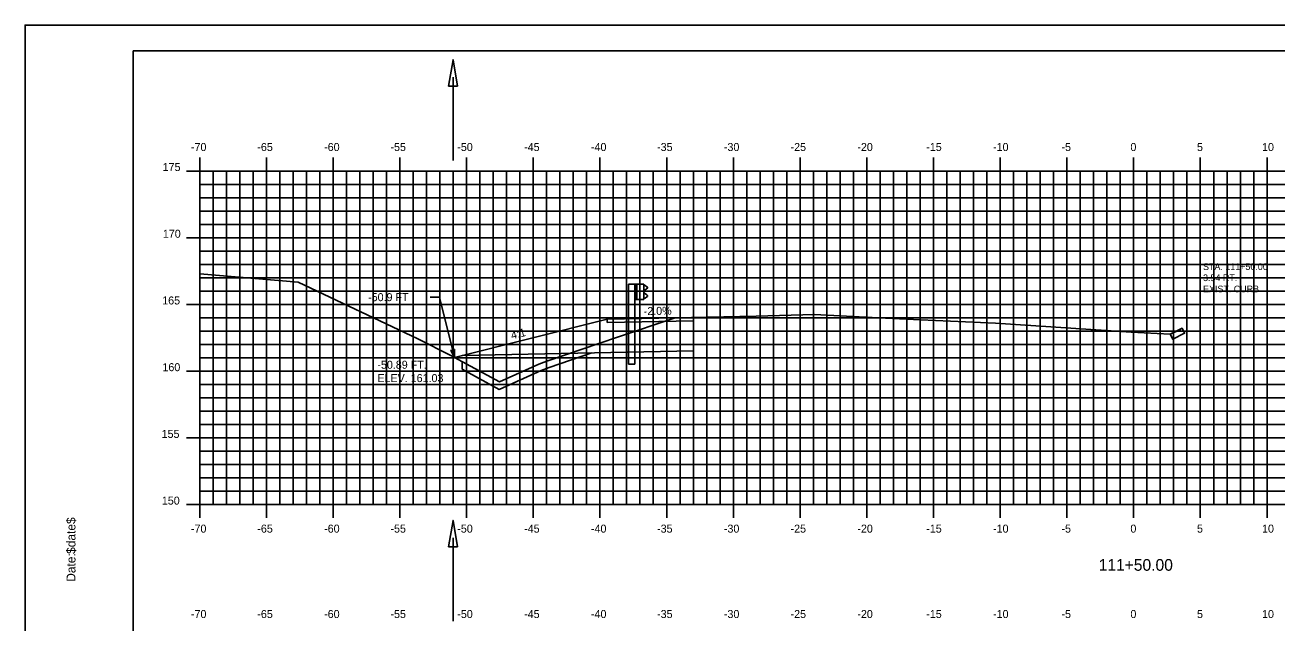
# Model space of a CAD drawing. Extents: x 1668473 to 1668643, y 337823 to 337933.
# Drawn here: x 1668472.7 to 1668566.5, y 337888.6 to 337933.4 of the extents above; entities that cross this region are included whole.
import ezdxf

# ---------------------------------------------------------------- set-up
doc = ezdxf.new("R2010")
doc.units = 0
for name, color, linetype in [('ANNOTATION', 7, 'Continuous'), ('BORDER', 7, 'Continuous'), ('D_Drainage_Ditch_Line', 7, 'Continuous'), ('D_Guardrail_Beam_Lt', 7, 'Continuous'), ('D_Roadway_Pavement', 7, 'Continuous'), ('D_Text_Monospaced', 7, 'Continuous'), ('D_Text_Standard', 7, 'Continuous'), ('Grubbing', 7, 'Continuous'), ('H_V ANNOTATION', 7, 'Continuous'), ('MAJOR', 7, 'Continuous'), ('MINOR', 7, 'Continuous'), ('PLOT BOUNDARY', 7, 'Continuous'), ('S_Curb_Type_5', 7, 'Continuous'), ('S_Roadway_Centerline', 7, 'Continuous')]:
    doc.layers.add(name, color=color, linetype=linetype)

msp = doc.modelspace()

# ---------------------------------------------------------------- linework, layer by layer
at = {"layer": 'ANNOTATION'}
msp.add_line((1668516.335, 337911.092), (1668516.335, 337911.342), dxfattribs=at)
at = {"layer": 'BORDER'}
for p, q in [((1668640.786, 337931.453), (1668480.786, 337931.453)), ((1668480.786, 337931.453), (1668480.786, 337826.453))]:
    msp.add_line(p, q, dxfattribs=at)
at = {"layer": 'D_Drainage_Ditch_Line'}
for p, q in [((1668504.771, 337929.478), (1668504.772, 337923.234)), ((1668504.771, 337894.955), (1668504.772, 337888.712))]:
    msp.add_line(p, q, dxfattribs=at)
for points in [[(1668504.443, 337928.822), (1668505.099, 337928.822), (1668504.771, 337930.79)], [(1668504.443, 337894.299), (1668505.099, 337894.299), (1668504.771, 337896.268)]]:
    msp.add_lwpolyline(points, close=True, dxfattribs=at)
at = {"layer": 'D_Guardrail_Beam_Lt'}
for p, q in [((1668517.916, 337913.986), (1668517.916, 337907.986)), ((1668518.387, 337913.986), (1668517.916, 337913.986)), ((1668519.075, 337913.986), (1668518.387, 337913.986)), ((1668518.387, 337913.986), (1668518.387, 337912.819)), ((1668518.45, 337913.986), (1668518.45, 337912.819)), ((1668518.554, 337913.986), (1668518.554, 337912.819)), ((1668519.075, 337912.819), (1668519.075, 337913.986)), ((1668519.075, 337913.902), (1668519.149, 337913.888)), ((1668519.079, 337913.438), (1668519.079, 337913.367)), ((1668519.308, 337913.638), (1668519.113, 337913.502)), ((1668519.113, 337913.303), (1668519.308, 337913.167)), ((1668519.165, 337913.881), (1668519.308, 337913.781)), ((1668518.387, 337912.819), (1668519.075, 337912.819)), ((1668518.408, 337907.986), (1668518.408, 337912.819)), ((1668519.149, 337912.917), (1668519.075, 337912.902)), ((1668519.308, 337913.024), (1668519.165, 337912.924)), ((1668518.408, 337907.986), (1668517.916, 337907.986))]:
    msp.add_line(p, q, dxfattribs=at)
for centre, major_axis, start_param, end_param in [((1668519.158, 337913.438), (-0.0789, 0), 5.323254, 6.283185), ((1668519.158, 337913.367), (-0.0789, 0), 6.283185, 7.243116), ((1668519.141, 337913.847), (0.0417, 0), 0.959931, 1.376053), ((1668519.258, 337913.71), (0.0877, 0), 5.323254, 7.243116), ((1668519.141, 337912.958), (0.0417, 0), 4.907132, 5.323254), ((1668519.258, 337913.095), (0.0877, 0), 5.323254, 7.243116)]:
    msp.add_ellipse(centre, major_axis=major_axis, ratio=0.995501, start_param=start_param, end_param=end_param, dxfattribs=at)
at = {"layer": 'D_Roadway_Pavement'}
for p, q in [((1668522.785, 337911.471), (1668516.335, 337911.342)), ((1668522.785, 337911.471), (1668522.785, 337911.221)), ((1668522.785, 337911.471), (1668522.785, 337908.971)), ((1668516.335, 337911.342), (1668504.893, 337908.482)), ((1668522.785, 337911.221), (1668516.335, 337911.092)), ((1668522.785, 337908.971), (1668505.466, 337908.625))]:
    msp.add_line(p, q, dxfattribs=at)
at = {"layer": 'D_Text_Standard'}
msp.add_lwpolyline([(1668504.893, 337908.482), (1668503.749, 337913.001), (1668503.069, 337913.001)], dxfattribs=at)
msp.add_lwpolyline([(1668504.893, 337908.482), (1668504.609, 337909.01), (1668504.891, 337909.082)], close=True, dxfattribs=at)
at = {"layer": 'Grubbing'}
msp.add_line((1668505.466, 337908.168), (1668505.466, 337907.598), dxfattribs=at)
msp.add_lwpolyline([(1668505.466, 337907.598), (1668508.232, 337906.092), (1668511.386, 337907.51), (1668511.971, 337907.725), (1668515.175, 337908.819)], dxfattribs=at)
at = {"layer": 'MAJOR'}
for p, q in [((1668485.785, 337923.455), (1668485.785, 337922.453)), ((1668490.785, 337923.455), (1668490.785, 337922.453)), ((1668495.785, 337923.455), (1668495.785, 337922.453)), ((1668500.785, 337923.455), (1668500.785, 337922.453)), ((1668505.785, 337923.455), (1668505.785, 337922.453)), ((1668510.785, 337923.455), (1668510.785, 337922.453)), ((1668515.785, 337923.455), (1668515.785, 337922.453)), ((1668520.785, 337923.455), (1668520.785, 337922.453)), ((1668525.785, 337923.455), (1668525.785, 337922.453)), ((1668530.785, 337923.455), (1668530.785, 337922.453)), ((1668535.785, 337923.455), (1668535.785, 337922.453)), ((1668540.785, 337923.455), (1668540.785, 337922.453)), ((1668545.785, 337923.455), (1668545.785, 337922.453)), ((1668550.785, 337923.455), (1668550.785, 337922.453)), ((1668555.785, 337923.455), (1668555.785, 337922.453)), ((1668560.785, 337923.455), (1668560.785, 337922.453)), ((1668565.785, 337923.455), (1668565.785, 337922.453)), ((1668484.783, 337922.453), (1668485.785, 337922.453)), ((1668485.785, 337922.453), (1668625.785, 337922.453)), ((1668485.785, 337897.453), (1668485.785, 337922.453)), ((1668485.785, 337897.453), (1668485.785, 337922.453)), ((1668485.785, 337922.453), (1668625.785, 337922.453)), ((1668490.785, 337897.453), (1668490.785, 337922.453)), ((1668495.785, 337897.453), (1668495.785, 337922.453)), ((1668500.785, 337897.453), (1668500.785, 337922.453)), ((1668505.785, 337897.453), (1668505.785, 337922.453)), ((1668510.785, 337897.453), (1668510.785, 337922.453)), ((1668515.785, 337897.453), (1668515.785, 337922.453)), ((1668520.785, 337897.453), (1668520.785, 337922.453)), ((1668525.785, 337897.453), (1668525.785, 337922.453)), ((1668530.785, 337897.453), (1668530.785, 337922.453)), ((1668535.785, 337897.453), (1668535.785, 337922.453)), ((1668540.785, 337897.453), (1668540.785, 337922.453)), ((1668545.785, 337897.453), (1668545.785, 337922.453)), ((1668550.785, 337897.453), (1668550.785, 337922.453)), ((1668555.785, 337897.453), (1668555.785, 337922.453)), ((1668560.785, 337897.453), (1668560.785, 337922.453)), ((1668565.785, 337897.453), (1668565.785, 337922.453)), ((1668484.783, 337917.453), (1668485.785, 337917.453)), ((1668485.785, 337917.453), (1668625.785, 337917.453)), ((1668484.783, 337912.453), (1668485.785, 337912.453)), ((1668485.785, 337912.453), (1668625.785, 337912.453)), ((1668484.783, 337907.453), (1668485.785, 337907.453)), ((1668485.785, 337907.453), (1668625.785, 337907.453)), ((1668484.783, 337902.453), (1668485.785, 337902.453)), ((1668485.785, 337902.453), (1668625.785, 337902.453)), ((1668484.783, 337897.453), (1668485.785, 337897.453)), ((1668485.785, 337897.453), (1668625.785, 337897.453)), ((1668485.785, 337897.453), (1668625.785, 337897.453)), ((1668485.785, 337896.451), (1668485.785, 337897.453)), ((1668490.785, 337896.451), (1668490.785, 337897.453)), ((1668495.785, 337896.451), (1668495.785, 337897.453)), ((1668500.785, 337896.451), (1668500.785, 337897.453)), ((1668505.785, 337896.451), (1668505.785, 337897.453)), ((1668510.785, 337896.451), (1668510.785, 337897.453)), ((1668515.785, 337896.451), (1668515.785, 337897.453)), ((1668520.785, 337896.451), (1668520.785, 337897.453)), ((1668525.785, 337896.451), (1668525.785, 337897.453)), ((1668530.785, 337896.451), (1668530.785, 337897.453)), ((1668535.785, 337896.451), (1668535.785, 337897.453)), ((1668540.785, 337896.451), (1668540.785, 337897.453)), ((1668545.785, 337896.451), (1668545.785, 337897.453)), ((1668550.785, 337896.451), (1668550.785, 337897.453)), ((1668555.785, 337896.451), (1668555.785, 337897.453)), ((1668560.785, 337896.451), (1668560.785, 337897.453)), ((1668565.785, 337896.451), (1668565.785, 337897.453))]:
    msp.add_line(p, q, dxfattribs=at)
at = {"layer": 'MINOR'}
for p, q in [((1668486.785, 337897.453), (1668486.785, 337922.453)), ((1668487.785, 337897.453), (1668487.785, 337922.453)), ((1668488.785, 337897.453), (1668488.785, 337922.453)), ((1668489.785, 337897.453), (1668489.785, 337922.453)), ((1668491.785, 337897.453), (1668491.785, 337922.453)), ((1668492.785, 337897.453), (1668492.785, 337922.453)), ((1668493.785, 337897.453), (1668493.785, 337922.453)), ((1668494.785, 337897.453), (1668494.785, 337922.453)), ((1668496.785, 337897.453), (1668496.785, 337922.453)), ((1668497.785, 337897.453), (1668497.785, 337922.453)), ((1668498.785, 337897.453), (1668498.785, 337922.453)), ((1668499.785, 337897.453), (1668499.785, 337922.453)), ((1668501.785, 337897.453), (1668501.785, 337922.453)), ((1668502.785, 337897.453), (1668502.785, 337922.453)), ((1668503.785, 337897.453), (1668503.785, 337922.453)), ((1668504.785, 337897.453), (1668504.785, 337922.453)), ((1668506.785, 337897.453), (1668506.785, 337922.453)), ((1668507.785, 337897.453), (1668507.785, 337922.453)), ((1668508.785, 337897.453), (1668508.785, 337922.453)), ((1668509.785, 337897.453), (1668509.785, 337922.453)), ((1668511.785, 337897.453), (1668511.785, 337922.453)), ((1668512.785, 337897.453), (1668512.785, 337922.453)), ((1668513.785, 337897.453), (1668513.785, 337922.453)), ((1668514.785, 337897.453), (1668514.785, 337922.453)), ((1668516.785, 337897.453), (1668516.785, 337922.453)), ((1668517.785, 337897.453), (1668517.785, 337922.453)), ((1668518.785, 337897.453), (1668518.785, 337922.453)), ((1668519.785, 337897.453), (1668519.785, 337922.453)), ((1668521.785, 337897.453), (1668521.785, 337922.453)), ((1668522.785, 337897.453), (1668522.785, 337922.453)), ((1668523.785, 337897.453), (1668523.785, 337922.453)), ((1668524.785, 337897.453), (1668524.785, 337922.453)), ((1668526.785, 337897.453), (1668526.785, 337922.453)), ((1668527.785, 337897.453), (1668527.785, 337922.453)), ((1668528.785, 337897.453), (1668528.785, 337922.453)), ((1668529.785, 337897.453), (1668529.785, 337922.453)), ((1668531.785, 337897.453), (1668531.785, 337922.453)), ((1668532.785, 337897.453), (1668532.785, 337922.453)), ((1668533.785, 337897.453), (1668533.785, 337922.453)), ((1668534.785, 337897.453), (1668534.785, 337922.453)), ((1668536.785, 337897.453), (1668536.785, 337922.453)), ((1668537.785, 337897.453), (1668537.785, 337922.453)), ((1668538.785, 337897.453), (1668538.785, 337922.453)), ((1668539.785, 337897.453), (1668539.785, 337922.453)), ((1668541.785, 337897.453), (1668541.785, 337922.453)), ((1668542.785, 337897.453), (1668542.785, 337922.453)), ((1668543.785, 337897.453), (1668543.785, 337922.453)), ((1668544.785, 337897.453), (1668544.785, 337922.453)), ((1668546.785, 337897.453), (1668546.785, 337922.453)), ((1668547.785, 337897.453), (1668547.785, 337922.453)), ((1668548.785, 337897.453), (1668548.785, 337922.453)), ((1668549.785, 337897.453), (1668549.785, 337922.453)), ((1668551.785, 337897.453), (1668551.785, 337922.453)), ((1668552.785, 337897.453), (1668552.785, 337922.453)), ((1668553.785, 337897.453), (1668553.785, 337922.453)), ((1668554.785, 337897.453), (1668554.785, 337922.453)), ((1668556.785, 337897.453), (1668556.785, 337922.453)), ((1668557.785, 337897.453), (1668557.785, 337922.453)), ((1668558.785, 337897.453), (1668558.785, 337922.453)), ((1668559.785, 337897.453), (1668559.785, 337922.453)), ((1668561.785, 337897.453), (1668561.785, 337922.453)), ((1668562.785, 337897.453), (1668562.785, 337922.453)), ((1668563.785, 337897.453), (1668563.785, 337922.453)), ((1668564.785, 337897.453), (1668564.785, 337922.453)), ((1668485.785, 337921.453), (1668625.785, 337921.453)), ((1668485.785, 337921.453), (1668486.787, 337921.453)), ((1668485.785, 337920.453), (1668625.785, 337920.453)), ((1668485.785, 337920.453), (1668486.787, 337920.453)), ((1668485.785, 337919.453), (1668625.785, 337919.453)), ((1668485.785, 337919.453), (1668486.787, 337919.453)), ((1668485.785, 337918.453), (1668625.785, 337918.453)), ((1668485.785, 337918.453), (1668486.787, 337918.453)), ((1668485.785, 337916.453), (1668625.785, 337916.453)), ((1668485.785, 337916.453), (1668486.787, 337916.453)), ((1668485.785, 337915.453), (1668625.785, 337915.453)), ((1668485.785, 337915.453), (1668486.787, 337915.453)), ((1668485.785, 337914.453), (1668625.785, 337914.453)), ((1668485.785, 337914.453), (1668486.787, 337914.453)), ((1668485.785, 337913.453), (1668625.785, 337913.453)), ((1668485.785, 337913.453), (1668486.787, 337913.453)), ((1668485.785, 337911.453), (1668625.785, 337911.453)), ((1668485.785, 337911.453), (1668486.787, 337911.453)), ((1668485.785, 337910.453), (1668625.785, 337910.453)), ((1668485.785, 337910.453), (1668486.787, 337910.453)), ((1668485.785, 337909.453), (1668625.785, 337909.453)), ((1668485.785, 337909.453), (1668486.787, 337909.453)), ((1668485.785, 337908.453), (1668625.785, 337908.453)), ((1668485.785, 337908.453), (1668486.787, 337908.453)), ((1668485.785, 337906.453), (1668625.785, 337906.453)), ((1668485.785, 337906.453), (1668486.787, 337906.453)), ((1668485.785, 337905.453), (1668625.785, 337905.453)), ((1668485.785, 337905.453), (1668486.787, 337905.453)), ((1668485.785, 337904.453), (1668625.785, 337904.453)), ((1668485.785, 337904.453), (1668486.787, 337904.453)), ((1668485.785, 337903.453), (1668625.785, 337903.453)), ((1668485.785, 337903.453), (1668486.787, 337903.453)), ((1668485.785, 337901.453), (1668625.785, 337901.453)), ((1668485.785, 337901.453), (1668486.787, 337901.453)), ((1668485.785, 337900.453), (1668625.785, 337900.453)), ((1668485.785, 337900.453), (1668486.787, 337900.453)), ((1668485.785, 337899.453), (1668625.785, 337899.453)), ((1668485.785, 337899.453), (1668486.787, 337899.453)), ((1668485.785, 337898.453), (1668625.785, 337898.453)), ((1668485.785, 337898.453), (1668486.787, 337898.453))]:
    msp.add_line(p, q, dxfattribs=at)
at = {"layer": 'PLOT BOUNDARY'}
msp.add_lwpolyline([(1668472.692, 337823.394), (1668642.692, 337823.394), (1668642.692, 337933.394), (1668472.692, 337933.394)], close=True, dxfattribs=at)
at = {"layer": 'S_Curb_Type_5'}
msp.add_lwpolyline([(1668558.529, 337910.219), (1668559.423, 337910.666), (1668559.609, 337910.294), (1668558.715, 337909.846)], close=True, dxfattribs=at)
at = {"layer": 'S_Roadway_Centerline'}
msp.add_lwpolyline([(1668485.785, 337914.755), (1668493.166, 337914.118), (1668502.142, 337909.876), (1668504.607, 337908.64), (1668505.156, 337908.337), (1668508.253, 337906.65), (1668511.197, 337907.973), (1668511.804, 337908.197), (1668517.091, 337910.001), (1668521.421, 337911.439), (1668527.482, 337911.584), (1668531.877, 337911.701), (1668536.657, 337911.461), (1668539.816, 337911.302), (1668545.443, 337911.046), (1668555.596, 337910.389), (1668558.529, 337910.219), (1668558.839, 337910.371), (1668559.321, 337910.541)], dxfattribs=at)

# ---------------------------------------------------------------- texts
at = {"layer": 'ANNOTATION'}
for s, rotation, p in [('-2.0%', 1.14576, (1668519.068, 337911.65)), ('4:1', 14.03624, (1668509.188, 337909.831))]:
    msp.add_text(s, height=0.6, rotation=rotation, dxfattribs=at).set_placement(p)
for s, p in [('C', (1668545.438, 337911.046)), ('L', (1668545.443, 337911.039))]:
    msp.add_text(s, height=0.0146, dxfattribs=at).set_placement(p)
at = {"layer": 'BORDER'}
for s, p in [('$date$', (1668476.471, 337893.759)), ('Date:', (1668476.471, 337891.67))]:
    msp.add_text(s, height=0.6696, rotation=90, dxfattribs=at).set_placement(p)
at = {"layer": 'D_Text_Monospaced'}
for s, height, p in [('STA. 111+50.00', 0.49998, (1668560.988, 337915.039)), ('3.54 RT.', 0.5, (1668560.988, 337914.205)), ('EXIST. CURB', 0.49998, (1668560.988, 337913.365))]:
    msp.add_text(s, height=height, dxfattribs=at).set_placement(p)
at = {"layer": 'D_Text_Standard'}
for s, p in [('-50.9 FT', (1668498.407, 337912.701)), ('-50.89 FT.', (1668499.101, 337907.635)), ('ELEV. 161.03', (1668499.101, 337906.635))]:
    msp.add_text(s, height=0.6, dxfattribs=at).set_placement(p)
at = {"layer": 'H_V ANNOTATION'}
for s, height, p in [('-70', 0.6, (1668485.127, 337923.953)), ('-65', 0.6, (1668490.103, 337923.953)), ('-60', 0.6, (1668495.111, 337923.953)), ('-55', 0.6, (1668500.082, 337923.953)), ('-50', 0.6, (1668505.09, 337923.953)), ('-45', 0.6, (1668510.103, 337923.953)), ('-40', 0.6, (1668515.111, 337923.953)), ('-35', 0.6, (1668520.066, 337923.953)), ('-30', 0.6, (1668525.074, 337923.953)), ('-25', 0.6, (1668530.071, 337923.953)), ('-20', 0.6, (1668535.079, 337923.953)), ('-15', 0.6, (1668540.242, 337923.953)), ('-10', 0.6, (1668545.25, 337923.953)), ('-5', 0.6, (1668550.376, 337923.953)), ('0', 0.6, (1668555.544, 337923.953)), ('5', 0.6, (1668560.536, 337923.953)), ('10', 0.6, (1668565.411, 337923.953)), ('175', 0.6, (1668483.006, 337922.453)), ('170', 0.6, (1668483.022, 337917.453)), ('165', 0.6, (1668482.974, 337912.453)), ('160', 0.6, (1668482.99, 337907.453)), ('155', 0.6, (1668482.931, 337902.453)), ('150', 0.6, (1668482.947, 337897.453)), ('-70', 0.6, (1668485.127, 337895.353)), ('-65', 0.6, (1668490.103, 337895.353)), ('-60', 0.6, (1668495.111, 337895.353)), ('-55', 0.6, (1668500.082, 337895.353)), ('-50', 0.6, (1668505.09, 337895.353)), ('-45', 0.6, (1668510.103, 337895.353)), ('-40', 0.6, (1668515.111, 337895.353)), ('-35', 0.6, (1668520.066, 337895.353)), ('-30', 0.6, (1668525.074, 337895.353)), ('-25', 0.6, (1668530.071, 337895.353)), ('-20', 0.6, (1668535.079, 337895.353)), ('-15', 0.6, (1668540.242, 337895.353)), ('-10', 0.6, (1668545.25, 337895.353)), ('-5', 0.6, (1668550.376, 337895.353)), ('0', 0.6, (1668555.544, 337895.353)), ('5', 0.6, (1668560.536, 337895.353)), ('10', 0.6, (1668565.411, 337895.353)), ('111+50.00', 0.875, (1668553.164, 337892.497)), ('-70', 0.6, (1668485.127, 337888.953)), ('-65', 0.6, (1668490.103, 337888.953)), ('-60', 0.6, (1668495.111, 337888.953)), ('-55', 0.6, (1668500.082, 337888.953)), ('-50', 0.6, (1668505.09, 337888.953)), ('-45', 0.6, (1668510.103, 337888.953)), ('-40', 0.6, (1668515.111, 337888.953)), ('-35', 0.6, (1668520.066, 337888.953)), ('-30', 0.6, (1668525.074, 337888.953)), ('-25', 0.6, (1668530.071, 337888.953)), ('-20', 0.6, (1668535.079, 337888.953)), ('-15', 0.6, (1668540.242, 337888.953)), ('-10', 0.6, (1668545.25, 337888.953)), ('-5', 0.6, (1668550.376, 337888.953)), ('0', 0.6, (1668555.544, 337888.953)), ('5', 0.6, (1668560.536, 337888.953)), ('10', 0.6, (1668565.411, 337888.953))]:
    msp.add_text(s, height=height, dxfattribs=at).set_placement(p)
at = {"layer": 'MAJOR'}
msp.add_text('-', height=0.006, dxfattribs=at).set_placement((1668485.781, 337897.453))

doc.saveas('drawing.dxf')
